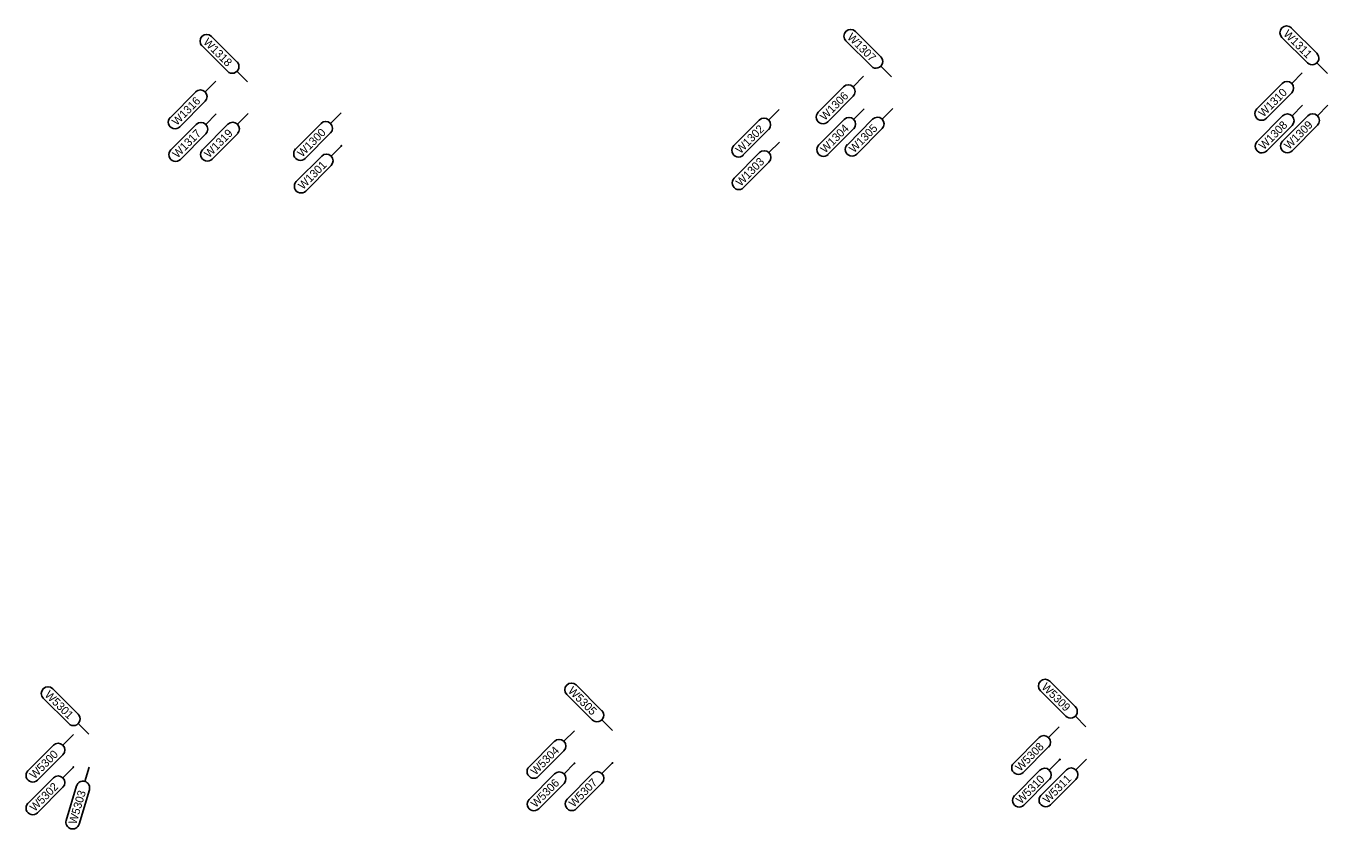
# Model space of a CAD drawing. Extents: x 12479652 to 12487250, y 9842710 to 9846560.
# Drawn here: x 12482037.2 to 12482236.9, y 9842727.8 to 9842851 of the extents above; entities that cross this region are included whole.
import ezdxf

# ---------------------------------------------------------------- set-up
doc = ezdxf.new("R2010")
doc.units = 0
doc.layers.add('_CIVIL_CONSTRUCTION', color=7, linetype='Continuous')
doc.layers.add('TextAlignmentLrg', color=7, linetype='Continuous')

msp = doc.modelspace()

# ---------------------------------------------------------------- linework, layer by layer
at = {"layer": '_CIVIL_CONSTRUCTION'}
for p, q in [((12482065.65, 9842849.37), (12482069.56, 9842845.48)), ((12482164.4, 9842850.14), (12482168.31, 9842846.25)), ((12482233.74, 9842845.32), (12482229.82, 9842849.21)), ((12482231.27, 9842850.66), (12482235.18, 9842846.78)), ((12482068.11, 9842844.02), (12482064.2, 9842847.91)), ((12482166.86, 9842844.8), (12482162.95, 9842848.69)), ((12482236.82, 9842843.7), (12482235.19, 9842845.32)), ((12482071.2, 9842842.41), (12482069.56, 9842844.03)), ((12482165.67, 9842843.28), (12482164.05, 9842841.64)), ((12482169.95, 9842843.18), (12482168.32, 9842844.8)), ((12482232.94, 9842843.8), (12482231.32, 9842842.17)), ((12482066.3, 9842842.5), (12482064.68, 9842840.87)), ((12482158.71, 9842837.73), (12482162.6, 9842841.64)), ((12482225.98, 9842838.25), (12482229.87, 9842842.17)), ((12482059.34, 9842836.95), (12482063.23, 9842840.86)), ((12482064.68, 9842839.42), (12482060.79, 9842835.5)), ((12482164.05, 9842840.19), (12482160.16, 9842836.28)), ((12482231.32, 9842840.72), (12482227.43, 9842836.81)), ((12482066.39, 9842837.5), (12482064.76, 9842835.87)), ((12482071.26, 9842837.54), (12482069.63, 9842835.9)), ((12482085.53, 9842837.65), (12482083.91, 9842836.02)), ((12482152.72, 9842838.17), (12482151.1, 9842836.54)), ((12482165.75, 9842838.28), (12482164.13, 9842836.64)), ((12482170.13, 9842838.31), (12482168.51, 9842836.68)), ((12482226.04, 9842833.25), (12482229.93, 9842837.17)), ((12482229.92, 9842833.28), (12482233.81, 9842837.2)), ((12482233, 9842838.8), (12482231.38, 9842837.17)), ((12482236.88, 9842838.83), (12482235.26, 9842837.2)), ((12482059.42, 9842831.95), (12482063.31, 9842835.86)), ((12482064.29, 9842831.99), (12482068.18, 9842835.9)), ((12482078.57, 9842832.1), (12482082.46, 9842836.01)), ((12482145.76, 9842832.63), (12482149.65, 9842836.54)), ((12482151.1, 9842835.09), (12482147.21, 9842831.18)), ((12482158.79, 9842832.73), (12482162.68, 9842836.64)), ((12482164.14, 9842835.19), (12482160.25, 9842831.28)), ((12482163.17, 9842832.76), (12482167.05, 9842836.67)), ((12482168.51, 9842835.23), (12482164.62, 9842831.31)), ((12482231.38, 9842835.72), (12482227.49, 9842831.81)), ((12482235.26, 9842835.75), (12482231.37, 9842831.84)), ((12482064.77, 9842834.42), (12482060.88, 9842830.5)), ((12482069.64, 9842834.45), (12482065.75, 9842830.54)), ((12482083.91, 9842834.57), (12482080.02, 9842830.65)), ((12482152.77, 9842833.17), (12482151.14, 9842831.54)), ((12482078.66, 9842827.1), (12482082.55, 9842831.01)), ((12482085.62, 9842832.65), (12482084, 9842831.02)), ((12482145.8, 9842827.63), (12482149.69, 9842831.54)), ((12482084, 9842829.57), (12482080.11, 9842825.65)), ((12482151.15, 9842830.09), (12482147.26, 9842826.18)), ((12482041.3, 9842749.29), (12482045.21, 9842745.4)), ((12482121.58, 9842749.87), (12482125.49, 9842745.98)), ((12482194.22, 9842750.44), (12482198.13, 9842746.55)), ((12482043.77, 9842743.95), (12482039.85, 9842747.83)), ((12482124.05, 9842744.52), (12482120.14, 9842748.41)), ((12482196.68, 9842745.09), (12482192.77, 9842748.98)), ((12482046.85, 9842742.33), (12482045.22, 9842743.95)), ((12482127.13, 9842742.91), (12482125.5, 9842744.53)), ((12482195.65, 9842743.44), (12482194.02, 9842741.81)), ((12482199.77, 9842743.47), (12482198.14, 9842745.1)), ((12482044.47, 9842742.26), (12482042.85, 9842740.63)), ((12482114.36, 9842737.31), (12482118.25, 9842741.23)), ((12482121.32, 9842742.86), (12482119.7, 9842741.23)), ((12482188.68, 9842737.89), (12482192.57, 9842741.81)), ((12482037.51, 9842736.71), (12482041.4, 9842740.62)), ((12482042.85, 9842739.18), (12482038.96, 9842735.26)), ((12482119.7, 9842739.78), (12482115.81, 9842735.87)), ((12482194.03, 9842740.36), (12482190.14, 9842736.45)), ((12482044.47, 9842737.26), (12482042.85, 9842735.63)), ((12482046.9, 9842737.28), (12482046.24, 9842735.08)), ((12482121.34, 9842737.86), (12482119.72, 9842736.23)), ((12482127.15, 9842737.91), (12482125.53, 9842736.27)), ((12482195.76, 9842738.44), (12482194.14, 9842736.81)), ((12482199.83, 9842738.48), (12482198.21, 9842736.84)), ((12482037.51, 9842731.71), (12482041.4, 9842735.62)), ((12482114.37, 9842732.31), (12482118.26, 9842736.23)), ((12482120.19, 9842732.36), (12482124.08, 9842736.27)), ((12482188.8, 9842732.89), (12482192.69, 9842736.81)), ((12482194.14, 9842735.36), (12482190.25, 9842731.45)), ((12482192.87, 9842732.93), (12482196.76, 9842736.84)), ((12482198.21, 9842735.39), (12482194.33, 9842731.48)), ((12482042.86, 9842734.18), (12482038.97, 9842730.26)), ((12482043.37, 9842729.1), (12482044.96, 9842734.39)), ((12482046.92, 9842733.8), (12482045.34, 9842728.51)), ((12482119.72, 9842734.78), (12482115.83, 9842730.87)), ((12482125.53, 9842734.82), (12482121.64, 9842730.91))]:
    msp.add_line(p, q, dxfattribs=at)
for centre, start, end in [((12482230.55, 9842849.94), 45.1702, 225.1702), ((12482064.92, 9842848.64), 45.1702, 225.1702), ((12482163.67, 9842849.41), 45.1702, 225.1702), ((12482068.84, 9842844.75), 225.1702, 45.1702), ((12482167.59, 9842845.52), 225.1702, 45.1702), ((12482234.46, 9842846.05), 225.1702, 45.1702), ((12482063.95, 9842840.14), 315.1702, 135.1702), ((12482163.33, 9842840.92), 315.1702, 135.1702), ((12482230.59, 9842841.44), 315.1702, 135.1702), ((12482159.44, 9842837), 135.1702, 315.1702), ((12482226.7, 9842837.53), 135.1702, 315.1702), ((12482230.66, 9842836.44), 315.1702, 135.1702), ((12482234.54, 9842836.47), 315.1702, 135.1702), ((12482060.06, 9842836.23), 135.1702, 315.1702), ((12482064.04, 9842835.14), 315.1702, 135.1702), ((12482068.91, 9842835.18), 315.1702, 135.1702), ((12482083.18, 9842835.29), 315.1702, 135.1702), ((12482150.38, 9842835.81), 315.1702, 135.1702), ((12482163.41, 9842835.92), 315.1702, 135.1702), ((12482167.78, 9842835.95), 315.1702, 135.1702), ((12482226.77, 9842832.53), 135.1702, 315.1702), ((12482230.65, 9842832.56), 135.1702, 315.1702), ((12482060.15, 9842831.23), 135.1702, 315.1702), ((12482065.02, 9842831.26), 135.1702, 315.1702), ((12482079.29, 9842831.38), 135.1702, 315.1702), ((12482083.28, 9842830.29), 315.1702, 135.1702), ((12482146.49, 9842831.9), 135.1702, 315.1702), ((12482150.42, 9842830.81), 315.1702, 135.1702), ((12482159.52, 9842832), 135.1702, 315.1702), ((12482163.89, 9842832.04), 135.1702, 315.1702), ((12482079.39, 9842826.38), 135.1702, 315.1702), ((12482146.53, 9842826.9), 135.1702, 315.1702), ((12482040.58, 9842748.56), 45.1702, 225.1702), ((12482120.86, 9842749.14), 45.1702, 225.1702), ((12482193.5, 9842749.71), 45.1702, 225.1702), ((12482044.49, 9842744.67), 225.1702, 45.1702), ((12482124.77, 9842745.25), 225.1702, 45.1702), ((12482197.41, 9842745.82), 225.1702, 45.1702), ((12482118.97, 9842740.5), 315.1702, 135.1702), ((12482193.3, 9842741.08), 315.1702, 135.1702), ((12482042.13, 9842739.9), 315.1702, 135.1702), ((12482115.08, 9842736.59), 135.1702, 315.1702), ((12482189.41, 9842737.17), 135.1702, 315.1702), ((12482038.24, 9842735.99), 135.1702, 315.1702), ((12482042.13, 9842734.9), 315.1702, 135.1702), ((12482118.99, 9842735.5), 315.1702, 135.1702), ((12482124.8, 9842735.55), 315.1702, 135.1702), ((12482193.42, 9842736.08), 315.1702, 135.1702), ((12482197.49, 9842736.12), 315.1702, 135.1702), ((12482045.94, 9842734.09), 343.2949, 163.2949), ((12482038.24, 9842730.99), 135.1702, 315.1702), ((12482115.1, 9842731.59), 135.1702, 315.1702), ((12482120.92, 9842731.63), 135.1702, 315.1702), ((12482189.53, 9842732.17), 135.1702, 315.1702), ((12482193.6, 9842732.2), 135.1702, 315.1702), ((12482044.36, 9842728.81), 163.2949, 343.2949)]:
    msp.add_arc(centre, 1.03, start, end, dxfattribs=at)
at = {"layer": 'TextAlignmentLrg'}
for centre in [(12482085.56, 9842832.58), (12482044.47, 9842737.26), (12482121.34, 9842737.86), (12482127.15, 9842737.91), (12482195.76, 9842738.44)]:
    msp.add_circle(centre, 0.05, dxfattribs=at)

# ---------------------------------------------------------------- texts
at = {"layer": '_CIVIL_CONSTRUCTION'}
for s, rotation, p in [('W1318', 315.1702, (12482064.3, 9842848.37)), ('W1307', 315.1702, (12482163.06, 9842849.13)), ('W1311', 315.1702, (12482229.95, 9842849.63)), ('W1310', 45.1702, (12482226.98, 9842836.9)), ('W1316', 45.1702, (12482060.33, 9842835.6)), ('W1306', 45.1702, (12482159.71, 9842836.37)), ('W1317', 45.1702, (12482060.43, 9842830.61)), ('W1319', 45.1702, (12482065.29, 9842830.64)), ('W1300', 45.1702, (12482079.56, 9842830.75)), ('W1302', 45.1702, (12482146.78, 9842831.29)), ('W1304', 45.1702, (12482159.78, 9842831.37)), ('W1305', 45.1702, (12482164.18, 9842831.42)), ('W1308', 45.1702, (12482227.04, 9842831.9)), ('W1309', 45.1702, (12482230.92, 9842831.93)), ('W1301', 45.1702, (12482079.69, 9842825.78)), ('W1303', 45.1702, (12482146.81, 9842826.28)), ('W5301', 315.1702, (12482039.98, 9842748.26)), ('W5305', 315.1702, (12482120.24, 9842748.86)), ('W5309', 315.1702, (12482192.87, 9842749.44)), ('W5300', 45.1702, (12482038.51, 9842735.36)), ('W5304', 45.1702, (12482115.35, 9842735.95)), ('W5308', 45.1702, (12482189.68, 9842736.54)), ('W5306', 45.1702, (12482115.37, 9842730.96)), ('W5307', 45.1702, (12482121.2, 9842731.02)), ('W5310', 45.1702, (12482189.8, 9842731.54)), ('W5311', 45.1702, (12482193.9, 9842731.61)), ('W5302', 45.1702, (12482038.53, 9842730.38)), ('W5303', 73.2949, (12482044.89, 9842728.39))]:
    msp.add_text(s, height=1.25, rotation=rotation, dxfattribs=at).set_placement(p)

doc.saveas('drawing.dxf')
